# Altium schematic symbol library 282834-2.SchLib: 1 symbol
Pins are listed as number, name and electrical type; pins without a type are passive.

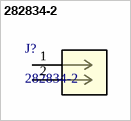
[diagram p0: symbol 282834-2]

## 282834-2
designator J?
TERMI-BLOK PCB MOUNT, 90 2P.; Manufacturer_Name: TE Connectivity
footprint CONN2_282834-2_TEC
pins: 1, 2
